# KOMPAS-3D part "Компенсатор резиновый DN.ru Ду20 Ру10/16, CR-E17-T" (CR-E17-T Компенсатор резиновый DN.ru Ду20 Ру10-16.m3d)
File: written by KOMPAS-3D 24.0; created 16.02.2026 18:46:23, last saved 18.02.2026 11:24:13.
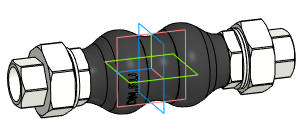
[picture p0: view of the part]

Document properties: Автор: DN.RU; Полное имя файла: CR-E17-T Компенсатор резиновый DN.ru Ду20 Ру10-16.cdw

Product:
- Body: Твердое тело1  | qty 1
    Масса: 1.995832
- Part/product: Компенсатор резиновый DN.ru Ду20 Ру10/16  | designation CR-E17-T
    Масса: 0.73
    Раздел спецификации: Прочие изделия
    Форматы листов документа: A3
    Комментарий: D140-02210
    Примечание: D140-02210
    additional columns: Типовые

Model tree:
1. Твердое тело1  (labels: Твердое тело1)

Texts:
  CR-E17-T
